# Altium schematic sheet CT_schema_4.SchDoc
size 368 x 245 mm
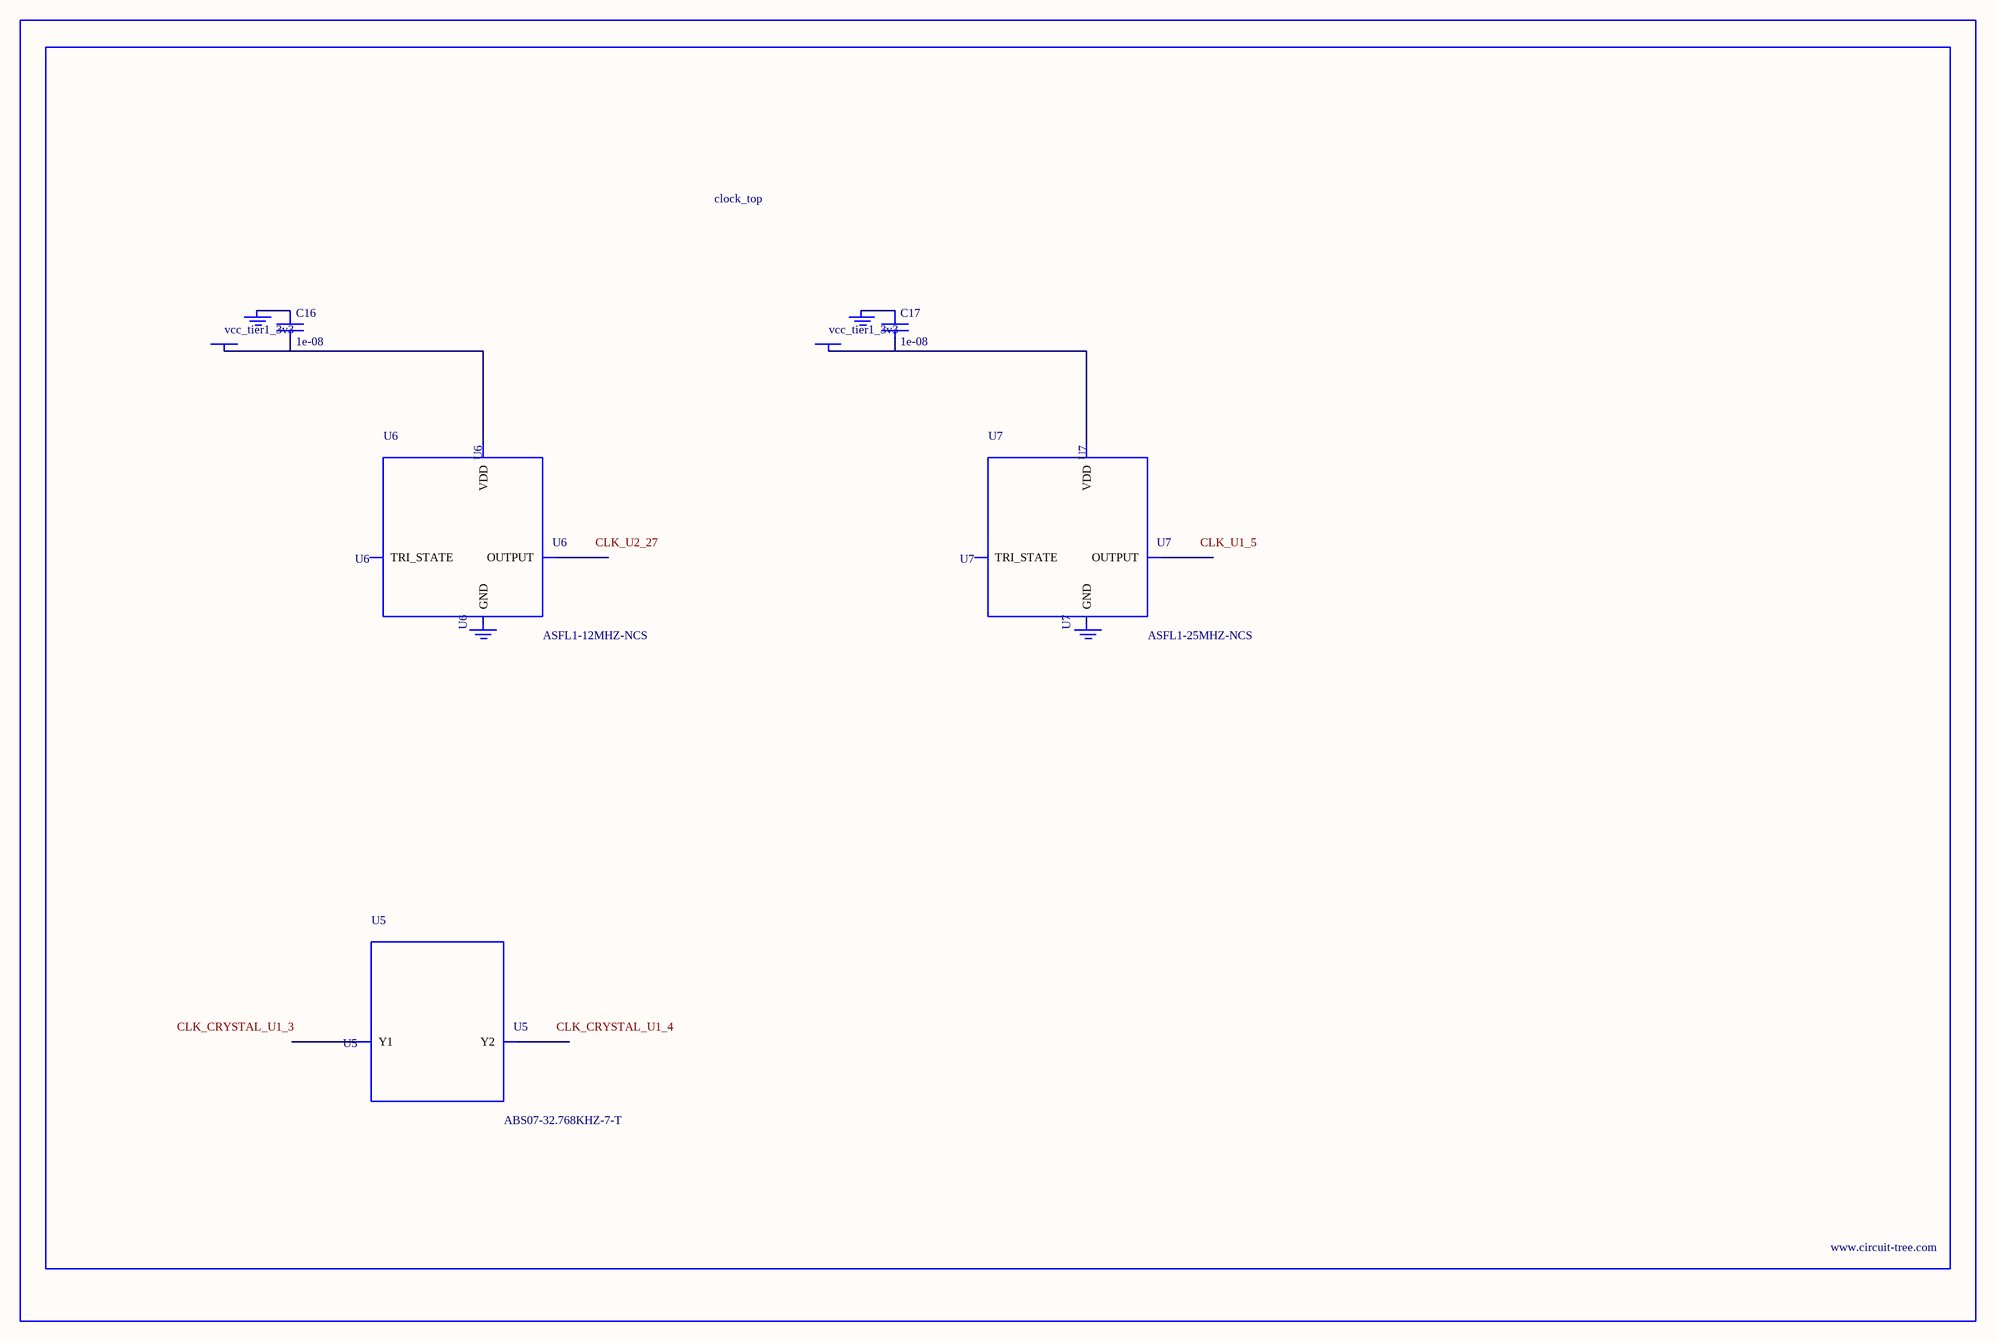
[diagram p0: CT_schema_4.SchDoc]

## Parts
BORDER3  (no value)
C16  1e-08  [C0402]
C17  1e-08  [C0402]
GND_INSTANCE_3_0  (no value)
GND_INSTANCE_3_1  (no value)
GND_INSTANCE_3_2  (no value)
GND_INSTANCE_3_3  (no value)
POWER_INSTANCE_3_0  vcc_tier1_3v3
POWER_INSTANCE_3_1  vcc_tier1_3v3
U5  ABS07-32.768KHZ-7-T  [ABS07-32.768KHZ-7-T]
U6  ASFL1-12MHZ-NCS  [ASFL1]
U7  ASFL1-25MHZ-NCS  [ASFL1]

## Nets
NetC16_1: C16.1 GND_INSTANCE_3_0.0(GND)
NetC16_2: C16.2 POWER_INSTANCE_3_0.0(PWR) U6.4(VDD)
NetC17_1: C17.1 GND_INSTANCE_3_2.0(GND)
NetC17_2: C17.2 POWER_INSTANCE_3_1.0(PWR) U7.4(VDD)

Not connected (* = marked no-connect by the designer): GND_INSTANCE_3_1 0(GND); GND_INSTANCE_3_3 0(GND); U5 1(Y1) 2(Y2); U6 1(TRI_STATE) 2(GND) 3(OUTPUT); U7 1(TRI_STATE) 2(GND) 3(OUTPUT)

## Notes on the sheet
- Labels drawn without touching a wire or pin: CLK_CRYSTAL_U1_3, CLK_CRYSTAL_U1_4, CLK_U1_5, CLK_U2_27

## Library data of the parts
BORDER3 = BORDER_PAGE3
C16 C17 = C0402C103K3RAC
GND_INSTANCE_3_0-GND_INSTANCE_3_3 = GND
POWER_INSTANCE_3_0 POWER_INSTANCE_3_1 = PWR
